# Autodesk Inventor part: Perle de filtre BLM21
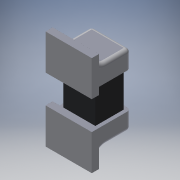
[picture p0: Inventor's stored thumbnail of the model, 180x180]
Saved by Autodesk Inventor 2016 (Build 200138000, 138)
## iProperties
Created: 2018-03
Part Number: Perle de filtre BLM21
Material: Générique
Document SubType Name: Modeling
Designer: Bruno
Density: 1 g/cm^3
Appearance: Par défaut
Author: Bruno
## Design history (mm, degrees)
feature "Composite1"
body "Srf1"
